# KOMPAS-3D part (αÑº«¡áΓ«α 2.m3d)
File: created 29.01.2016 13:47:21, last saved 26.07.2016 13:55:11.
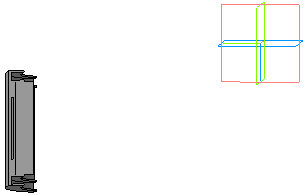
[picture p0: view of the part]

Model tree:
1. Эскиз:1
2. Операция выдавливания:1
     Толщина стенки 1 = 2; Толщина стенки 2 = 8; Расстояние 1 = 1
3. Эскиз:2
4. Операция выдавливания:2
     Толщина стенки 1 = 2; Толщина стенки 2 = 8; Расстояние 1 = 5
5. Эскиз:3
6. Операция выдавливания:3
     Толщина стенки 1 = 2; Толщина стенки 2 = 8; Расстояние 1 = 1
7. Эскиз:4
8. Операция выдавливания:4
     Толщина стенки 1 = 2; Толщина стенки 2 = 2.5; Расстояние 1 = 50
9. Эскиз:5
10. Вырезать элемент выдавливания:1
     Толщина стенки 2 = 1.2; Расстояние 1 = 40
11. Эскиз:6
12. Операция выдавливания:5
     Толщина стенки 1 = 2; Толщина стенки 2 = 2.5; Расстояние 1 = 10
13. Эскиз:7
14. Операция выдавливания:6
     Толщина стенки 1 = 2; Толщина стенки 2 = 8; Расстояние 1 = 1
15. Эскиз:8
16. Операция выдавливания:7
     Толщина стенки 1 = 2; Толщина стенки 2 = 8; Расстояние 1 = 5
17. Эскиз:9
18. Операция выдавливания:8
     Толщина стенки 1 = 2; Толщина стенки 2 = 8; Расстояние 1 = 1
19. Эскиз:10
20. Вырезать элемент выдавливания:2
     Толщина стенки 2 = 1.2; Расстояние 1 = 23
21. Эскиз:11
22. Вырезать элемент выдавливания:3
     Толщина стенки 2 = 1.2; Расстояние 1 = 1
23. Эскиз:12
24. Вырезать элемент выдавливания:4
     Расстояние 1 = 100
25. Эскиз:14
26. Операция выдавливания:10
     Расстояние 1 = 10; Расстояние 2 = 0.4
27. Эскиз:15
28. Операция выдавливания:11
     Расстояние 1 = 10; Расстояние 2 = 0.4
